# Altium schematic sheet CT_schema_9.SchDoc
size 287 x 160 mm
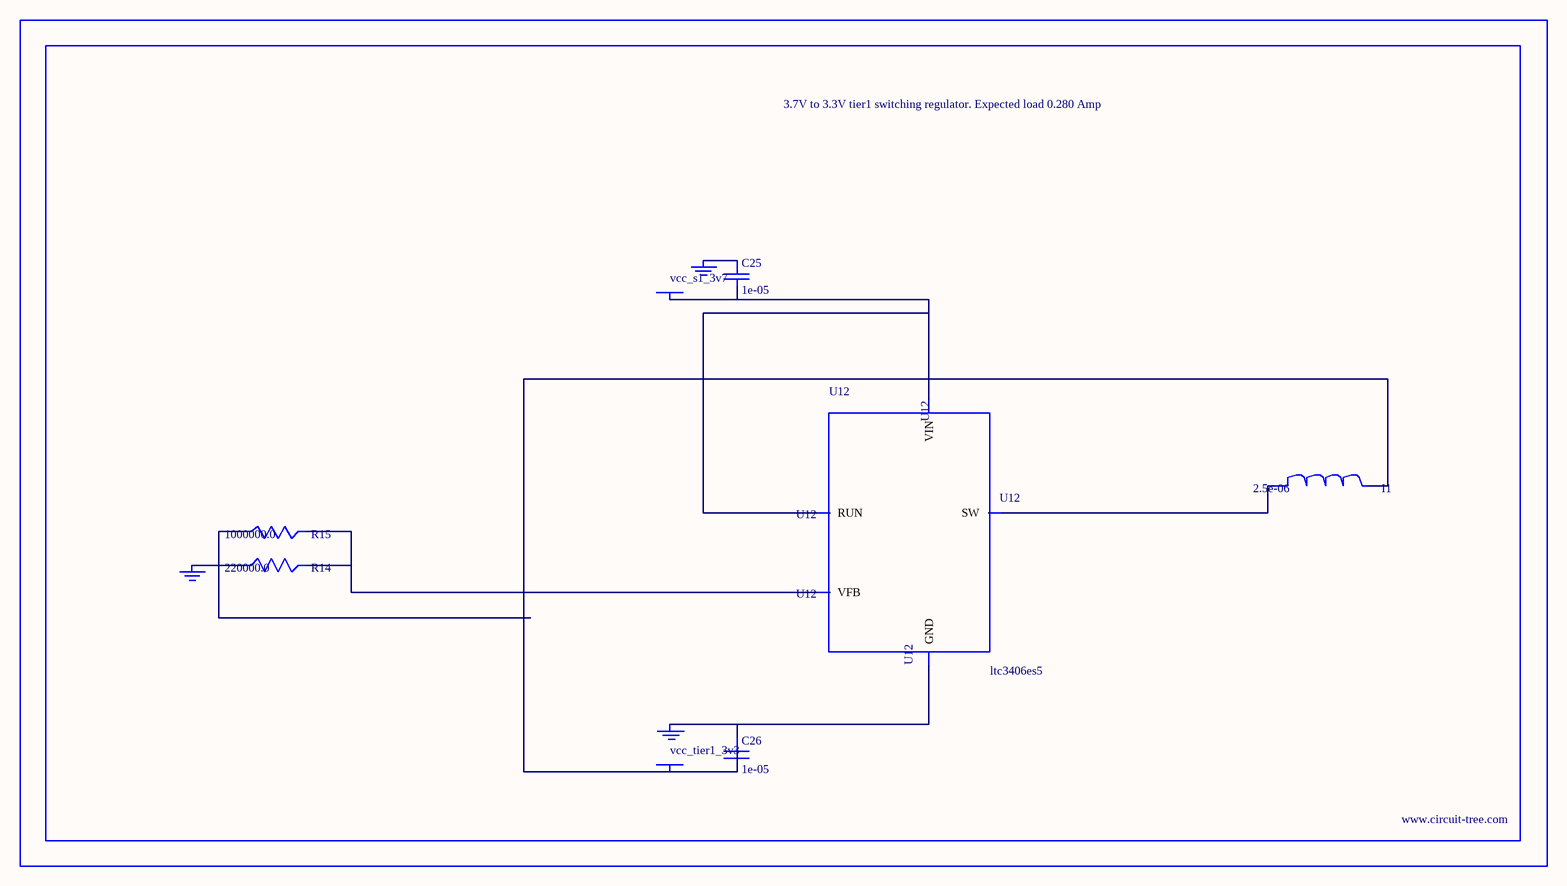
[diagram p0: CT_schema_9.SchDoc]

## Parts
BORDER8  (no value)
C25  1e-05  [C0805]
C26  1e-05  [C0805]
GND_INSTANCE_8_0  (no value)
GND_INSTANCE_8_1  (no value)
GND_INSTANCE_8_2  (no value)
I1  2.5e-06  [DR1040]
POWER_INSTANCE_8_0  vcc_tier1_3v3
POWER_INSTANCE_8_1  vcc_s1_3v7
R14  220000.0  [R0603]
R15  1000000.0  [R0603]
U12  ltc3406es5  [TSOT-23-5]

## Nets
NetC25_1: C25.1 GND_INSTANCE_8_1.0(GND)
NetC25_2: C25.2 POWER_INSTANCE_8_1.0(PWR) U12.1(RUN) U12.4(VIN)
NetC26_1: C26.1 GND_INSTANCE_8_0.0(GND) U12.2(GND)
NetC26_2: C26.2 I1.2 POWER_INSTANCE_8_0.0(PWR) R15.1
NetGND_INSTANCE_8_2_0: GND_INSTANCE_8_2.0(GND) R14.1
NetI1_1: I1.1 U12.3(SW)
NetR14_2: R14.2 R15.2 U12.5(VFB)

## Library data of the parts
BORDER8 = BORDER_PAGE8
C25 C26 = C0805C106K8RACTU
GND_INSTANCE_8_0-GND_INSTANCE_8_2 = GND
I1 = DR1040-2R5-R
POWER_INSTANCE_8_0 POWER_INSTANCE_8_1 = PWR
R14 = RC0603JR-07220KL
R15 = RC0603JR-071ML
